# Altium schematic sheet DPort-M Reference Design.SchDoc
size A4; CheckedBy: 工控机; Author: 工控机; SheetNumber: 01; PageSetup: Record=PageOptions¦CenterHorizontal=True¦CenterVertical=True¦PrintScale=1.00¦XCorrection=1.00¦YCorrection=1.00¦PrintKind=0¦BorderSize=5000000¦LeftOffset=0¦BottomOffset=0¦Orientation=2¦PaperLength=1000¦PaperWidth=1000¦Scale=100¦PaperSource=7¦PrintQuality=600¦MediaType=1¦DitherType=10¦PaperKind=A4¦PrintScaleMode=1; DesignDate: 2023.12.21; CheckDate: 2023.12.21; SheetName: DPort-M 参考设计电路; SheetVersion: Rev.A; SheetDescription: 集成PHY和网络变压器的RJ45插座; ProductName: 集成式RJ45插座; ProductModel: DPort-M
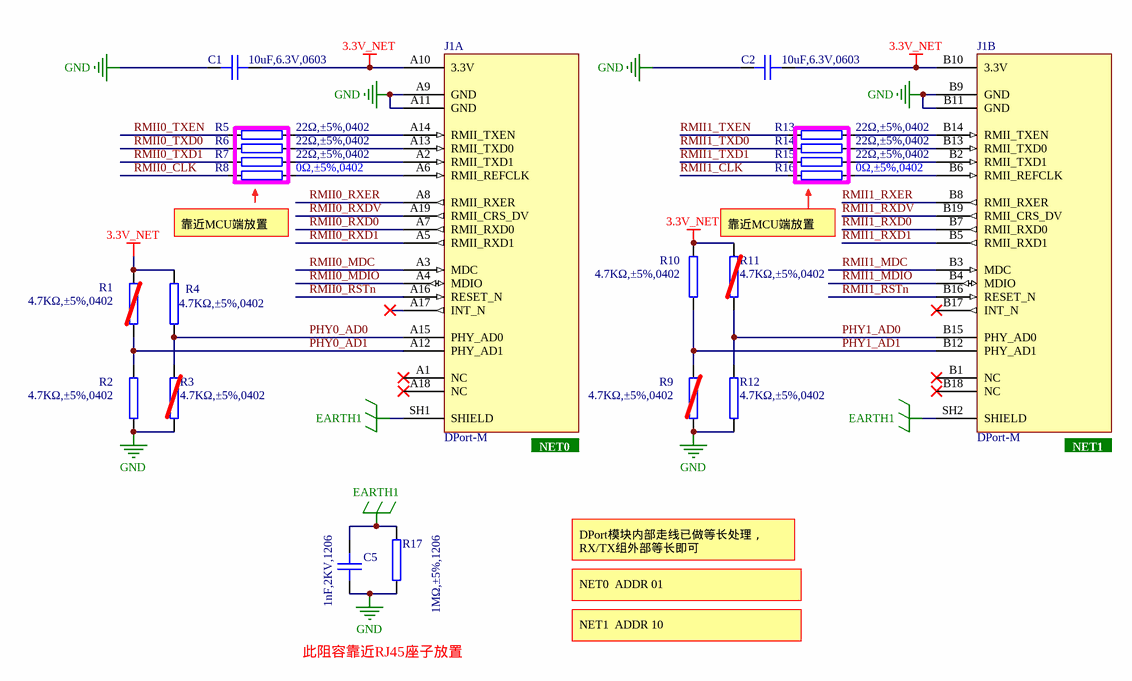
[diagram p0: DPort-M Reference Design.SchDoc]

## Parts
C1  10uF,6.3V,0603  [0603C]
C2  10uF,6.3V,0603  [0603C]
C5  1nF,2KV,1206  [1206C]
J1  DPort-M  [DPort-M]  (parts A,B of 2)
R1  4.7KΩ,±5%,0402  [0402R]
R2  4.7KΩ,±5%,0402  [0402R]
R3  4.7KΩ,±5%,0402  [0402R]
R4  4.7KΩ,±5%,0402  [0402R]
R5  22Ω,±5%,0402  [0402R]
R6  22Ω,±5%,0402  [0402R]
R7  22Ω,±5%,0402  [0402R]
R8  0Ω,±5%,0402  [0402R]
R9  4.7KΩ,±5%,0402  [0402R]
R10  4.7KΩ,±5%,0402  [0402R]
R11  4.7KΩ,±5%,0402  [0402R]
R12  4.7KΩ,±5%,0402  [0402R]
R13  22Ω,±5%,0402  [0402R]
R14  22Ω,±5%,0402  [0402R]
R15  22Ω,±5%,0402  [0402R]
R16  0Ω,±5%,0402  [0402R]
R17  1MΩ,±5%,1206  [1206R]

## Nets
3.3V_NET: C1.2 C2.2 J1.A10(3.3V) J1.B10(3.3V) R1.2 R4.2 R10.2 R11.2
EARTH1: C5.2 J1.SH1(SHIELD) J1.SH2(SHIELD) R17.2
GND: C1.1 C2.1 C5.1 J1.A9(GND) J1.A11(GND) J1.B9(GND) J1.B11(GND) R2.1 R3.1 R9.1 R12.1 R17.1
PHY0_AD0: J1.A15(PHY_AD0) R3.2 R4.1
PHY0_AD1: J1.A12(PHY_AD1) R1.1 R2.2
PHY1_AD0: J1.B15(PHY_AD0) R11.1 R12.2
PHY1_AD1: J1.B12(PHY_AD1) R9.2 R10.1
RMII0_CLK: R8.1
RMII0_MDC: J1.A3(MDC)
RMII0_MDIO: J1.A4(MDIO)
RMII0_RSTn: J1.A16(RESET_N)
RMII0_RXD0: J1.A7(RMII_RXD0)
RMII0_RXD1: J1.A5(RMII_RXD1)
RMII0_RXDV: J1.A19(RMII_CRS_DV)
RMII0_RXER: J1.A8(RMII_RXER)
RMII0_TXD0: R6.1
RMII0_TXD1: R7.1
RMII0_TXEN: R5.1
RMII1_CLK: R16.1
RMII1_MDC: J1.B3(MDC)
RMII1_MDIO: J1.B4(MDIO)
RMII1_RSTn: J1.B16(RESET_N)
RMII1_RXD0: J1.B7(RMII_RXD0)
RMII1_RXD1: J1.B5(RMII_RXD1)
RMII1_RXDV: J1.B19(RMII_CRS_DV)
RMII1_RXER: J1.B8(RMII_RXER)
RMII1_TXD0: R14.1
RMII1_TXD1: R15.1
RMII1_TXEN: R13.1
NetJ1_A2: J1.A2(RMII_TXD1) R7.2
NetJ1_A6: J1.A6(RMII_REFCLK) R8.2
NetJ1_A13: J1.A13(RMII_TXD0) R6.2
NetJ1_A14: J1.A14(RMII_TXEN) R5.2
NetJ1_B2: J1.B2(RMII_TXD1) R15.2
NetJ1_B6: J1.B6(RMII_REFCLK) R16.2
NetJ1_B13: J1.B13(RMII_TXD0) R14.2
NetJ1_B14: J1.B14(RMII_TXEN) R13.2

Not connected (* = marked no-connect by the designer): J1 A1(NC)* A17(INT_N)* A18(NC)* B1(NC)* B17(INT_N)* B18(NC)*

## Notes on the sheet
- 靠近MCU端放置
- NET0
- NET1
- DPort模块内部走线已做等长处理，
  RX/TX组外部等长即可
- NET0  ADDR 01
- NET1  ADDR 10
- 此阻容靠近RJ45座子放置

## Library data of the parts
C1 C2 = 02.01.00155: GRM188R60J106M****,0603,MURATA,10uF,X5R,±20%,6.3V,; 旧物料代码: 1.02.01.0065; 名称: 电容; 封装: 0603; 贴片和直插: SMT; 环保状态: RoHS2.0+REACH; 器件优选方案: 通用物料; 生产单位: PCS
C5 = 02.01.00212: CC1206KKX7RDBB102,1206,YAGEO,1nF,X7R,±10%,2KV,; 名称: 电容; 封装: 1206; 贴片和直插: SMT; 旧物料代码: 1.02.03.0003; 器件优选方案: 不推荐使用
R1-R4 R9-R12 = 01.01.00003: RTT02472JTH,0402,RALEC,4.7KΩ,±5%,1/16W,; 名称: 电阻; 封装: 0402; 贴片和直插: SMT; 旧物料代码: 1.01.17.0019; 环保状态: RoHS2.0+REACH; 器件优选方案: 通用物料; 生产单位: PCS
R5-R7 R13-R15 = 01.01.00014: RTT02220JTH,0402,RALEC,22Ω,±5%,1/16W,; 旧物料代码: 1.01.17.0023; 名称: 电阻; 封装: 0402; 贴片和直插: SMT; 环保状态: RoHS2.0+REACH; 器件优选方案: 通用物料; 生产单位: PCS
R8 R16 = 01.01.00004: RTT02000JTH,0402,RALEC,0Ω,±5%,1/16W,; 旧物料代码: 1.01.17.0004; 名称: 电阻; 封装: 0402; 贴片和直插: SMT; 器件优选方案: 通用物料; 现有库存: 428204
R17 = 01.01.00041: RTT06105JTP,1206,RALEC,1MΩ,±5%,1/4W,; 名称: 电阻; 封装: 1206; 贴片和直插: SMT; 旧物料代码: 1.01.03.0019; 器件优选方案: 通用物料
